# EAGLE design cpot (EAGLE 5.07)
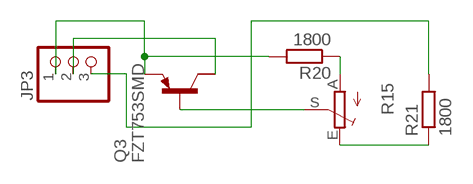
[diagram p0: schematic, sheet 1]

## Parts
JP3  PINHD-1X3  [1X03]
Q3  FZT753SMD  [SOT223]
R15  TRIM_EU-RAND160  [RANDL]
R20  1800  R-EU_R0805  [R0805]
R21  1800  R-EU_R0805  [R0805]

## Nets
C: JP3.2 Q3.2(C)
N$4: Q3.1(B) R15.S
N$5: R15.A R20.1
N$10: R15.E R21.1
N$14: JP3.1 Q3.3(E) R20.2
N$22: JP3.3 R21.2
Unconnected: Q3.4(C/)

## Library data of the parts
JP3 = pinhead:PINHD-1X3: PIN HEADER
Q3 = transistor-pnp:FZT753SMD: PNP Transistor
R15 = pot:TRIM_EU-: POTENTIOMETER
R20 R21 = rcl:R-EU_: RESISTOR, European symbol

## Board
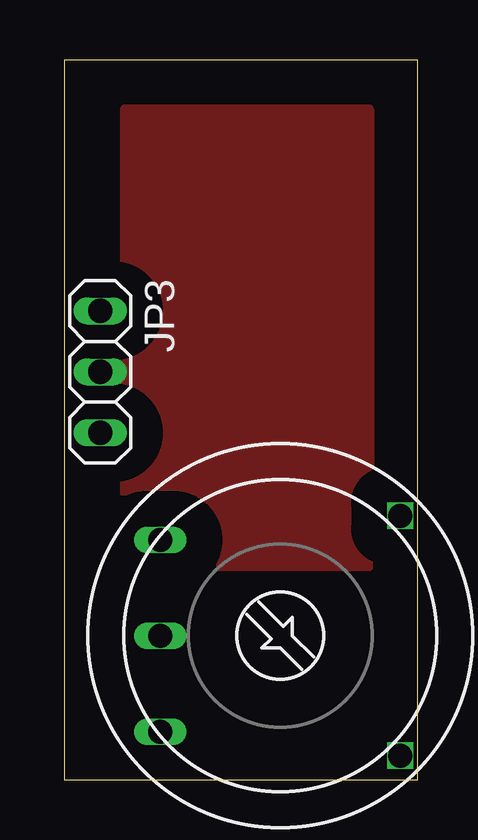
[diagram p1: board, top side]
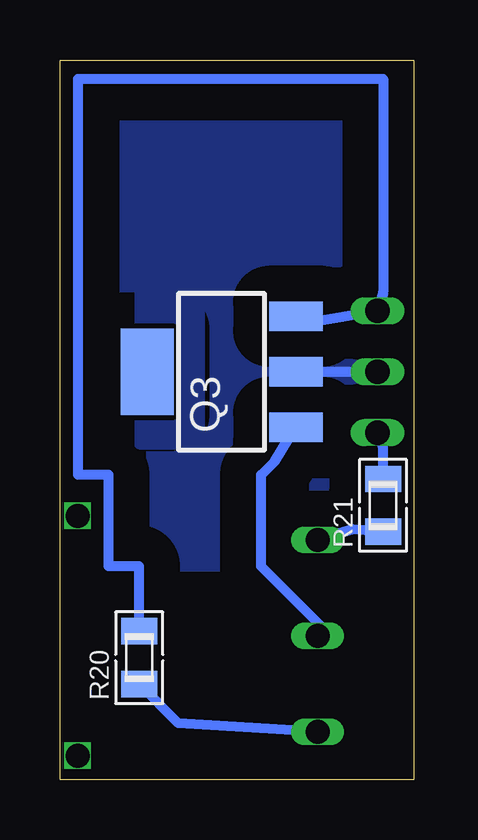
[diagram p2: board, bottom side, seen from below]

Size 14.73 x 30 mm. Coordinates in mm from the lower left corner, seen from the top.
Outline: 0,0 14.73,0 14.73,30 0,30 0,0
Copper layers (1*16): Top 0.035mm / dielectric 1.5mm / Bottom 0.035mm
Design rules "default": minimum track width 10mil, minimum drill 20mil, track to track 8mil, track to pad 8mil, pad to pad 8mil, via to via 8mil, smd to smd 8mil, copper to edge 40mil, drill to drill 8mil, minimum pad ring 1mil, minimum via ring 8mil, stop-mask expansion 4mil, vias tented up to drill 0mil, thermal gap 10mil

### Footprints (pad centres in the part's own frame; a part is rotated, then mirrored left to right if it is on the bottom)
1X03 = drill 1.016 long: 1 -2.54,0; 2 0,0; 3 2.54,0
SOT223 = smd 1.219 x 2.235: 1 -2.311,-3.099; 2 0,-3.099; 3 2.311,-3.099 | smd 3.6 x 2.2: 4 0,3.099
RANDL = drill 1 long: A -4,5; E 4,5; S 0,5 | drill 1 square: P$1 -5,-5; P$2 5,-5
R0805 = smd 1.1 x 1.5: 1 -1.1,0; 2 1.1,0

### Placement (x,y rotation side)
JP3  1.5,17 270 top
Q3  8,17 90 bottom
R15  9,6 90 top
R20  11.43,5.08 90 bottom
R21  1.27,11.43 90 bottom

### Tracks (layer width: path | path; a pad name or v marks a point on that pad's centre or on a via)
C
  Bottom 0.406: JP3.2 Q3.2
  pour Bottom (isolate 1.5, no thermals): 2.54,27.94 12.7,27.94 12.7,8.89 2.54,8.89
  pour Bottom (no thermals): 8.89,20.32 11.43,20.32 11.43,13.97 8.89,13.97
  pour Bottom (no thermals): 8.89,20.32 11.43,20.32 11.43,13.97 8.89,13.97
  pour Top (isolate 1.5, no thermals): 2.54,27.94 12.7,27.94 12.7,8.89 2.54,8.89
N$4
  Bottom 0.406: Q3.1 5.79,13.26 6.35,12.7 6.35,8.89 3.81,6.35 R15.S
N$5
  Bottom 0.406: R15.A 9.8,2.35 R20.1
N$10
  Bottom 0.406: R21.1 2.54,10.43 R15.E
N$14
  Bottom 0.406: R20.2 11.43,8.89 12.7,8.89 12.7,12.7 13.97,12.7 13.97,29.21 1.27,29.21 1.27,20.32 JP3.1 4.29,19.05 Q3.3
N$22
  Bottom 0.406: JP3.3 1.27,13.8 R21.2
